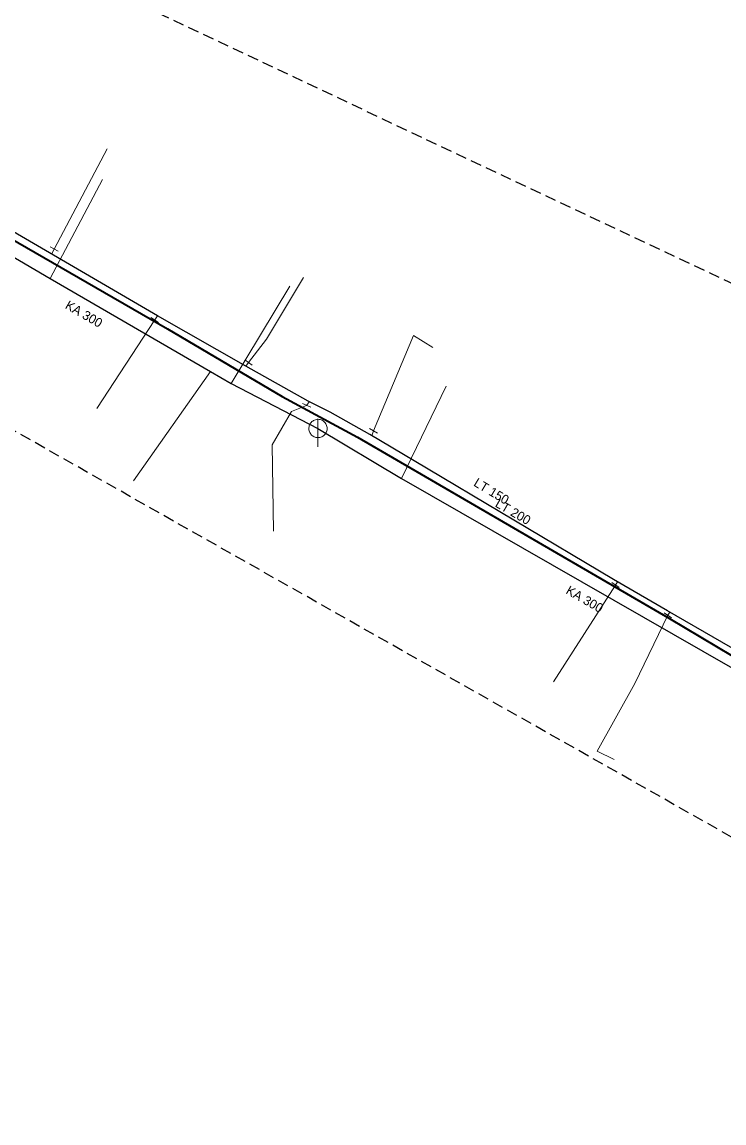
# Model space of a CAD drawing. Extents: x -749365 to -748625, y -965388 to -964881.
# Drawn here: x -749212.4 to -749135.6, y -965069 to -964948.5 of the extents above; entities that cross this region are included whole.
import ezdxf

# ---------------------------------------------------------------- set-up
doc = ezdxf.new("R2010")
doc.units = 0
doc.header["$LTSCALE"] = 0.4
doc.linetypes.add('MEDIUM_DASHED', pattern=[4.5, 3, -1.5])
for name, color, linetype, lineweight in [('1', 7, 'MEDIUM_DASHED', 25), ('11', 7, 'Continuous', 13), ('13', 7, 'Continuous', 13), ('14', 7, 'Continuous', 13), ('17', 7, 'Continuous', 25), ('22', 7, 'Continuous', 13), ('34', 7, 'Continuous', 13)]:
    doc.layers.add(name, color=color, linetype=linetype, lineweight=lineweight)

msp = doc.modelspace()

# ---------------------------------------------------------------- linework, layer by layer
at = {"layer": '1'}
for points in [[(-749332.669, -964883.965), (-749106.184, -964990.559), (-749105.322, -964991.077), (-749104.58, -964991.757), (-749103.99, -964992.571), (-749103.575, -964993.487), (-749094.514, -965020.387), (-748844.275, -965150.977)], [(-748913.896, -965162.751), (-749358.2, -964911.234)]]:
    msp.add_lwpolyline(points, dxfattribs=at)
at = {"layer": '11'}
for p, q in [((-749203.633, -964965.77), (-749209.362, -964976.622)), ((-749183.122, -964977.428), (-749189.541, -964988.087)), ((-749200.238, -964998.728), (-749191.81, -964986.765)), ((-749166.006, -964988.396), (-749170.903, -964998.5))]:
    msp.add_line(p, q, dxfattribs=at)
at = {"layer": '13'}
for p, q in [((-749208.925, -964973.381), (-749203.109, -964962.436)), ((-749197.903, -964981.144), (-749204.228, -964990.831)), ((-749147.464, -965010.142), (-749154.241, -965020.749))]:
    msp.add_line(p, q, dxfattribs=at)
for points in [[(-749187.641, -964985.801), (-749185.665, -964983.259), (-749181.616, -964976.489)], [(-749173.948, -964993.284), (-749169.567, -964982.842), (-749167.46, -964984.138)], [(-749181.291, -964990.489), (-749182.931, -964991.146), (-749185.059, -964994.793), (-749184.921, -965004.263)], [(-749141.739, -965013.455), (-749145.353, -965020.903), (-749149.463, -965028.306), (-749147.616, -965029.243)]]:
    msp.add_lwpolyline(points, dxfattribs=at)
at = {"layer": '14'}
for p, q in [((-749209.21, -964973.927), (-749208.925, -964973.381)), ((-749197.61, -964980.691), (-749197.903, -964981.144)), ((-749187.92, -964986.181), (-749187.641, -964985.801)), ((-749180.981, -964990.08), (-749181.291, -964990.489)), ((-749174.129, -964993.826), (-749173.948, -964993.284)), ((-749147.232, -965009.804), (-749147.464, -965010.142)), ((-749141.506, -965013.106), (-749141.739, -965013.455))]:
    msp.add_line(p, q, dxfattribs=at)
at = {"layer": '14', "lineweight": 25}
for points in [[(-749218.834, -964971.068), (-749209.362, -964976.622), (-749191.809, -964986.765), (-749189.541, -964988.087), (-749180.034, -964993.011)], [(-749180.034, -964993.011), (-749170.903, -964998.5), (-749127.898, -965023.089)]]:
    msp.add_lwpolyline(points, dxfattribs=at)
at = {"layer": '17'}
msp.add_lwpolyline([(-749129.897, -965019.83), (-749141.763, -965012.953), (-749147.67, -965009.555), (-749169.498, -964996.566), (-749174.36, -964993.689), (-749178.686, -964991.22), (-749181.107, -964990.017), (-749187.92, -964986.181), (-749197.61, -964980.691), (-749208.557, -964974.308), (-749219.081, -964968.169), (-749222.514, -964968.719), (-749229.989, -964964.651), (-749252.214, -964952.116), (-749254.966, -964950.395)], dxfattribs=at)
at = {"layer": '17', "lineweight": 35}
msp.add_lwpolyline([(-749218.876, -964969.25), (-749196.521, -964982.106), (-749183.951, -964989.517), (-749175.703, -964993.951), (-749141.565, -965013.806), (-749129.553, -965020.95), (-749117.313, -965027.865), (-749111.826, -965031.374), (-749105.952, -965034.92), (-749090.077, -965044.286), (-749082.192, -965048.943), (-749077.271, -965051.641), (-749068.54, -965056.298), (-749056.263, -965063.706)], dxfattribs=at)
at = {"layer": '22'}
msp.add_line((-749180.034, -964995.011), (-749180.033, -964992.011), dxfattribs=at)
msp.add_lwpolyline([(-749179.034, -964993.011), (-749179.039, -964992.902), (-749179.057, -964992.794), (-749179.087, -964992.688), (-749179.127, -964992.587), (-749179.179, -964992.49), (-749179.241, -964992.4), (-749179.313, -964992.317), (-749179.393, -964992.243), (-749179.481, -964992.177), (-749179.575, -964992.122), (-749179.675, -964992.077), (-749179.78, -964992.044), (-749179.887, -964992.022), (-749179.996, -964992.012), (-749180.106, -964992.014), (-749180.214, -964992.028), (-749180.321, -964992.053), (-749180.424, -964992.09), (-749180.522, -964992.139), (-749180.614, -964992.197), (-749180.7, -964992.266), (-749180.777, -964992.343), (-749180.846, -964992.429), (-749180.905, -964992.521), (-749180.953, -964992.619), (-749180.99, -964992.722), (-749181.016, -964992.829), (-749181.03, -964992.937), (-749181.033, -964993.047), (-749181.023, -964993.156), (-749181.002, -964993.263), (-749180.968, -964993.367), (-749180.924, -964993.467), (-749180.869, -964993.562), (-749180.803, -964993.65), (-749180.729, -964993.73), (-749180.646, -964993.802), (-749180.556, -964993.864), (-749180.46, -964993.916), (-749180.358, -964993.957), (-749180.253, -964993.987), (-749180.145, -964994.005), (-749180.035, -964994.011), (-749179.926, -964994.005), (-749179.818, -964993.987), (-749179.713, -964993.958), (-749179.611, -964993.917), (-749179.514, -964993.865), (-749179.424, -964993.803), (-749179.341, -964993.732), (-749179.266, -964993.652), (-749179.201, -964993.564), (-749179.145, -964993.47), (-749179.101, -964993.37), (-749179.067, -964993.266), (-749179.045, -964993.158), (-749179.035, -964993.049)], close=True, dxfattribs=at)
at = {"layer": '34'}
for p, q in [((-749209.368, -964973.15), (-749208.481, -964973.612)), ((-749197.482, -964981.414), (-749198.322, -964980.872)), ((-749188.044, -964985.505), (-749187.238, -964986.097)), ((-749180.834, -964990.693), (-749181.747, -964990.283)), ((-749174.378, -964993.029), (-749173.518, -964993.539)), ((-749147.051, -965010.424), (-749147.875, -965009.858)), ((-749141.322, -965013.731), (-749142.154, -965013.177))]:
    msp.add_line(p, q, dxfattribs=at)

# ---------------------------------------------------------------- texts
at = {"layer": '1'}
for s, rotation, p in [('KA 300', 330, (-749207.8, -964979.824)), ('LT 150', 329, (-749163.084, -964999.231)), ('LT 200', 330, (-749160.731, -965001.518)), ('KA 300', 330, (-749152.99, -965011.027))]:
    msp.add_text(s, height=1, rotation=rotation, dxfattribs=at).set_placement(p)

doc.saveas('drawing.dxf')
